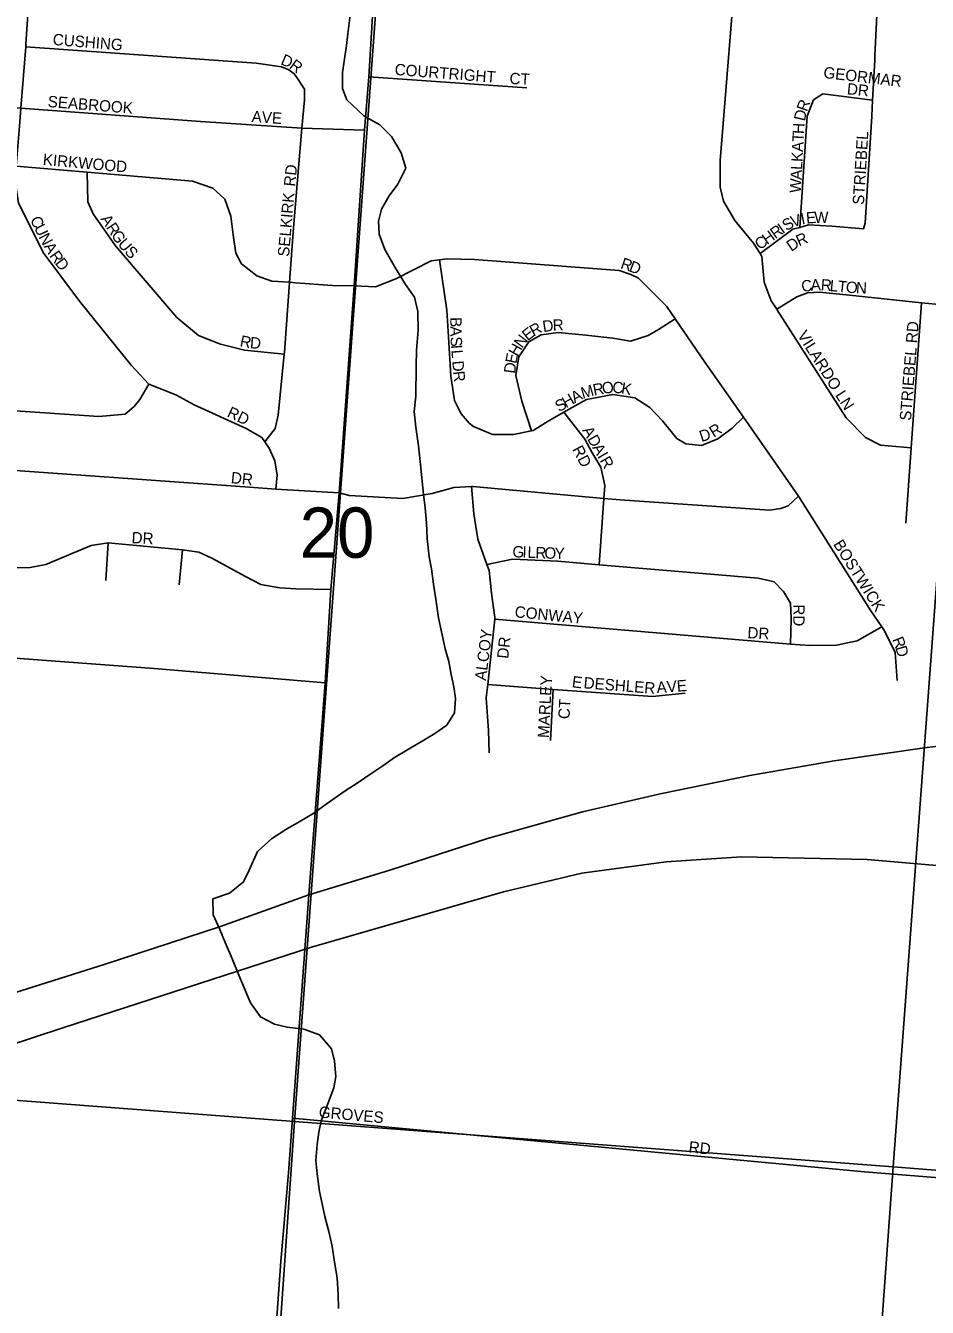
# Model space of a CAD drawing. Extents: x 0 to 34, y 0 to 22.
# Drawn here: x 5.595 to 6.347, y 18.975 to 20.042 of the extents above; entities that cross this region are included whole.
import ezdxf

# ---------------------------------------------------------------- set-up
doc = ezdxf.new("R2010")
doc.units = 0
for name, color, linetype in [('GM_X_City_Street', 7, 'Continuous'), ('GM_X_City_Street_Text', 7, 'Continuous'), ('GM_X_Interstate_Route', 7, 'Continuous'), ('GM_X_Minor_River', 7, 'Continuous'), ('GM_X_Rail_Line', 7, 'Continuous'), ('GM_X_Section', 7, 'Continuous'), ('GM_X_Section_Text', 7, 'Continuous')]:
    doc.layers.add(name, color=color, linetype=linetype)

msp = doc.modelspace()

# ---------------------------------------------------------------- linework, layer by layer
at = {"layer": 'GM_X_City_Street'}
for points in [[(5.8036, 19.6561), (5.8045, 19.6679), (5.8027, 19.6797), (5.7979, 19.6904), (5.7943, 19.6956), (5.7919, 19.6992), (5.7787, 19.7066), (5.7353, 19.7265), (5.7202, 19.7346), (5.6977, 19.7437), (5.6829, 19.7593), (5.6398, 19.8127), (5.6095, 19.8533), (5.5891, 19.8946), (5.5863, 19.9128), (5.5872, 19.9251), (5.5898, 19.9584), (5.591, 19.9736), (5.595, 20.0245), (5.5952, 20.0268), (5.6037, 20.1551)], [(5.8813, 20.0039), (5.889, 20.1337)], [(6.2229, 19.803), (6.221, 19.8061), (6.2165, 19.8131), (6.2106, 19.8287), (6.2086, 19.85), (6.2071, 19.8524), (6.2018, 19.8611), (6.1861, 19.8799), (6.1768, 19.896), (6.1739, 19.9078), (6.1738, 19.9299), (6.1886, 20.1117)], [(6.3027, 20.0134), (6.3029, 20.0172), (6.3069, 20.1022)], [(5.595, 20.0245), (5.7871, 20.0109), (5.8083, 20.008), (5.8144, 20.0053), (5.8189, 20.0022), (5.8204, 19.9999)], [(6.2935, 19.873), (6.2947, 19.8776), (6.3002, 19.9669), (6.3009, 19.9801), (6.3027, 20.0134)], [(5.7943, 19.6956), (5.803, 19.7067), (5.8054, 19.7177), (5.8104, 19.7685), (5.8106, 19.7701), (5.8149, 19.8285), (5.8182, 19.8738), (5.8253, 19.9567), (5.8274, 19.9805), (5.8275, 19.9892), (5.8204, 19.9999)], [(5.8447, 19.4949), (5.8493, 19.5725), (5.8563, 19.6532), (5.8687, 19.8255), (5.8774, 19.9551), (5.881, 19.9996), (5.8813, 20.0039)], [(5.881, 19.9996), (6.0126, 19.9905)], [(5.4485, 19.9847), (5.4785, 19.9823), (5.5353, 19.9778), (5.5551, 19.9763), (5.591, 19.9736), (5.7406, 19.9624), (5.8253, 19.9567), (5.8774, 19.9551)], [(6.2402, 19.8741), (6.2463, 19.9667), (6.2518, 19.9803)], [(6.2518, 19.9803), (6.2594, 19.9855), (6.3009, 19.9801)], [(5.5872, 19.9251), (5.6463, 19.9201), (5.734, 19.9127), (5.751, 19.9068), (5.7611, 19.8976), (5.7659, 19.8835), (5.768, 19.8679), (5.7701, 19.8526), (5.7749, 19.8438), (5.7877, 19.8338), (5.8002, 19.8295), (5.8149, 19.8285), (5.8199, 19.8281), (5.8507, 19.8259), (5.8687, 19.8255), (5.8867, 19.8247), (5.9035, 19.8314), (5.9329, 19.8463), (5.9398, 19.8472), (5.9462, 19.848), (5.969, 19.8474), (6.0896, 19.8384), (6.0994, 19.8349), (6.1058, 19.8318)], [(5.6463, 19.9201), (5.6468, 19.8954), (5.6513, 19.8855), (5.67, 19.8587), (5.7209, 19.7992), (5.739, 19.7842), (5.7575, 19.7768), (5.7775, 19.772), (5.8104, 19.7685)], [(6.2071, 19.8524), (6.2346, 19.8726), (6.2402, 19.8741), (6.2476, 19.8762), (6.2669, 19.8752), (6.2935, 19.873)], [(5.9648, 19.711), (5.958, 19.719), (5.9525, 19.7301), (5.9493, 19.7503), (5.9474, 19.783), (5.9461, 19.8051), (5.9398, 19.8472)], [(6.3215, 19.4968), (6.3198, 19.52), (6.3109, 19.538), (6.3086, 19.5414), (6.2994, 19.5548), (6.2393, 19.6502), (6.1934, 19.7162), (6.1612, 19.762), (6.1365, 19.7981), (6.1291, 19.8087), (6.1182, 19.8195), (6.1058, 19.8318)], [(6.221, 19.8061), (6.2378, 19.8163), (6.2466, 19.8196), (6.2568, 19.8202), (6.2818, 19.8177), (6.3418, 19.8113), (6.3535, 19.8103), (6.36, 19.8097)], [(6.3287, 19.6279), (6.3331, 19.6905), (6.3418, 19.8113)], [(6.0167, 19.7048), (6.0086, 19.7295), (6.0036, 19.7508), (6.006, 19.7664), (6.0145, 19.7788), (6.0248, 19.7848), (6.0389, 19.7866), (6.062, 19.7844), (6.0844, 19.7819), (6.0992, 19.7794), (6.114, 19.7842), (6.1224, 19.7891), (6.1365, 19.7981)], [(6.3331, 19.6905), (6.3074, 19.6927), (6.2949, 19.6993), (6.2788, 19.7155), (6.2237, 19.8018), (6.2229, 19.803)], [(5.5824, 19.7216), (5.6559, 19.7168), (5.6779, 19.7187), (5.6855, 19.7251), (5.6901, 19.7308), (5.6977, 19.7437)], [(5.9648, 19.711), (5.9682, 19.7083), (5.984, 19.7016), (6.0015, 19.7018), (6.0167, 19.7048), (6.0179, 19.7051), (6.032, 19.7137), (6.0437, 19.7203), (6.0626, 19.7308), (6.0843, 19.7351), (6.1028, 19.7323), (6.1153, 19.7241), (6.1258, 19.713), (6.1377, 19.6984), (6.1453, 19.6938), (6.1582, 19.6925), (6.1719, 19.698), (6.1838, 19.707), (6.1934, 19.7162)], [(6.0731, 19.5932), (6.077, 19.6485), (6.0777, 19.6592), (6.0745, 19.6744), (6.067, 19.687), (6.0611, 19.6978), (6.0437, 19.7203)], [(5.295, 19.7051), (5.3014, 19.6952), (5.3158, 19.6927), (5.3556, 19.6896), (5.5301, 19.6759), (5.5471, 19.6746), (5.7816, 19.6579), (5.8036, 19.6561), (5.8563, 19.6532), (5.8646, 19.6509), (5.9094, 19.6485), (5.9337, 19.6524), (5.952, 19.6575), (5.9667, 19.6584), (5.9676, 19.6585), (6.077, 19.6485), (6.0905, 19.6473), (6.2149, 19.6386), (6.2244, 19.6401), (6.2305, 19.6423), (6.2393, 19.6502)], [(5.9814, 19.4364), (5.9809, 19.455), (5.9789, 19.4824), (5.9801, 19.4933), (5.986, 19.5479), (5.9861, 19.5492), (5.9833, 19.5694), (5.9812, 19.5884), (5.9795, 19.5933), (5.972, 19.6144), (5.9685, 19.6357), (5.9667, 19.6584)], [(5.5768, 19.5906), (5.5986, 19.5908), (5.6119, 19.5933), (5.6344, 19.6029), (5.6497, 19.6092), (5.6637, 19.6113), (5.7258, 19.6055), (5.7392, 19.6037), (5.7501, 19.5986), (5.7781, 19.5835), (5.7909, 19.5768), (5.8068, 19.574), (5.8201, 19.5731), (5.8493, 19.5725)], [(5.6619, 19.5802), (5.6637, 19.6113)], [(5.7229, 19.5765), (5.7258, 19.6055)], [(5.9795, 19.5933), (6.0007, 19.5977), (6.0386, 19.5961), (6.0731, 19.5932), (6.2055, 19.5821), (6.2188, 19.5789), (6.2267, 19.5709), (6.2326, 19.5613), (6.2332, 19.5484), (6.2324, 19.5271)], [(5.1165, 19.5549), (5.2089, 19.5439), (5.3102, 19.5362), (5.3432, 19.5337), (5.4554, 19.5251), (5.702, 19.5068), (5.8447, 19.4949)], [(5.986, 19.5479), (6.2324, 19.5271), (6.2485, 19.5258), (6.2709, 19.5263), (6.2881, 19.5299), (6.3086, 19.5414)], [(5.8137, 19.0835), (5.814, 19.0866), (5.8173, 19.1321), (5.8311, 19.3182), (5.8447, 19.4949)], [(5.9801, 19.4933), (6.0348, 19.4894), (6.1175, 19.4835), (6.1448, 19.4863)], [(6.0324, 19.4468), (6.0348, 19.4894)], [(5.8173, 19.1321), (6.2942, 19.0874), (6.8177, 19.0455)], [(5.7871, 18.7424), (5.7915, 18.7961), (5.7957, 18.8469), (5.8078, 19.0127), (5.8137, 19.0835)]]:
    msp.add_lwpolyline(points, dxfattribs=at)
at = {"layer": 'GM_X_Interstate_Route'}
msp.add_lwpolyline([(5.515, 19.2145), (5.6613, 19.2604), (5.7565, 19.2916), (5.8311, 19.3182), (5.8985, 19.3388), (5.98, 19.3651), (6.059, 19.3874), (6.1254, 19.4026), (6.1987, 19.4177), (6.2689, 19.4298), (6.3443, 19.4407), (6.4452, 19.453), (6.6369, 19.476), (6.6854, 19.482), (6.8515, 19.5006)], dxfattribs=at)
at = {"layer": 'GM_X_Minor_River'}
for points in [[(5.8591, 20.0033), (5.8604, 20.0127), (5.8624, 20.0256), (5.8636, 20.0355), (5.8669, 20.062)], [(5.8558, 18.9738), (5.8555, 18.9852), (5.8545, 18.9993), (5.8524, 19.0122), (5.8506, 19.0255), (5.8477, 19.0377), (5.8444, 19.0502), (5.8422, 19.0609), (5.84, 19.0711), (5.8379, 19.0859), (5.8369, 19.097), (5.8381, 19.1102), (5.8394, 19.1205), (5.8414, 19.1299), (5.8456, 19.1405), (5.8518, 19.1576), (5.8534, 19.167), (5.8524, 19.1796), (5.8499, 19.1899), (5.8398, 19.2017), (5.8269, 19.2064), (5.8129, 19.208), (5.8024, 19.2104), (5.7907, 19.2165), (5.7825, 19.2284), (5.7728, 19.2512), (5.7673, 19.2645), (5.7614, 19.2786), (5.7569, 19.2893), (5.7514, 19.3015), (5.7511, 19.3148), (5.7648, 19.3196), (5.7766, 19.329), (5.7813, 19.3388), (5.7882, 19.3543), (5.8, 19.3649), (5.8119, 19.3727), (5.8229, 19.3791), (5.8351, 19.3862), (5.8454, 19.3937), (5.8614, 19.405), (5.8721, 19.4117), (5.8827, 19.4189), (5.8926, 19.4256), (5.9025, 19.4327), (5.9128, 19.4387), (5.9254, 19.4462), (5.9361, 19.4526), (5.946, 19.4597), (5.9525, 19.4699), (5.9534, 19.4817), (5.952, 19.4916), (5.9498, 19.5018), (5.9476, 19.5125), (5.9447, 19.5231), (5.9421, 19.5349), (5.9392, 19.549), (5.9371, 19.5627), (5.935, 19.5771), (5.9332, 19.5897), (5.9314, 19.5999), (5.9297, 19.6151), (5.929, 19.6277), (5.928, 19.6406), (5.9266, 19.6516), (5.9252, 19.6656), (5.9238, 19.6793), (5.9224, 19.6922), (5.9203, 19.7078), (5.9189, 19.7207), (5.9202, 19.7336), (5.9204, 19.7583), (5.9209, 19.772), (5.9222, 19.7887), (5.922, 19.8042), (5.9191, 19.816), (5.9116, 19.8267), (5.9023, 19.8416), (5.8945, 19.8557), (5.8897, 19.8686), (5.889, 19.8793), (5.8917, 19.8895), (5.8979, 19.9005), (5.9052, 19.9103), (5.9118, 19.9235), (5.9081, 19.9364), (5.8999, 19.9498), (5.8901, 19.9597), (5.877, 19.9671), (5.8627, 19.9805), (5.859, 19.99), (5.8591, 20.0033)]]:
    msp.add_lwpolyline(points, dxfattribs=at)
at = {"layer": 'GM_X_Rail_Line'}
msp.add_lwpolyline([(3.2423, 18.4276), (4.0405, 18.6814), (4.9172, 18.9741), (5.626, 19.2074), (5.8332, 19.2746), (5.9934, 19.3207), (6.0587, 19.3362), (6.1289, 19.3456), (6.1917, 19.3498), (6.2964, 19.3477), (6.6636, 19.3159)], dxfattribs=at)
at = {"layer": 'GM_X_Section'}
for points in [[(5.3911, 20.1713), (5.8928, 20.1355), (5.819, 19.1295), (5.3184, 19.1674)], [(5.8928, 20.1355), (6.3931, 20.0998), (6.3181, 19.0917), (5.819, 19.1295)], [(6.3931, 20.0998), (6.8995, 20.0595), (6.8218, 19.0519), (6.3181, 19.0917)], [(5.819, 19.1295), (5.7484, 18.1169), (5.2507, 18.1559), (5.3184, 19.1674)], [(6.3181, 19.0917), (6.2447, 18.0791), (6.2087, 18.0808), (5.7484, 18.1169), (5.819, 19.1295)], [(6.3181, 19.0917), (6.8218, 19.0519), (6.7511, 18.0375), (6.2447, 18.0791)]]:
    msp.add_lwpolyline(points, close=True, dxfattribs=at)

# ---------------------------------------------------------------- texts
at = {"layer": 'GM_X_City_Street_Text'}
for s, rotation, p in [('CUSHING', 355.3919, (5.6173, 20.0262)), ('D', 337.1918, (5.8069, 20.0102)), ('R', 323.9851, (5.8141, 20.0073)), ('COURTRIGHT', 355.5526, (5.9023, 20.0012)), ('GEORMAR', 353.387, (6.2596, 19.9987)), ('CT', 356.8222, (5.9981, 19.9937)), ('DR', 353.9832, (6.2792, 19.9851)), ('SEABROOK', 355.4286, (5.6131, 19.9745)), ('R', 70.1768, (6.2462, 19.97)), ('AVE', 356.0569, (5.7831, 19.962)), ('D', 76.9313, (6.2444, 19.9622)), ('H', 87.0631, (6.2438, 19.9518)), ('A', 87.0631, (6.243, 19.9369)), ('T', 87.0631, (6.2434, 19.9452)), ('STRIEBEL', 86.477, (6.2937, 19.8928)), ('KIRKWOOD', 354.8056, (5.609, 19.9262)), ('K', 87.0631, (6.2426, 19.9285)), ('RD', 83.9832, (5.8195, 19.9079)), ('A', 87.0631, (6.2418, 19.9136)), ('L', 87.0631, (6.2422, 19.9219)), ('W', 87.0631, (6.2412, 19.9027)), ('SELKIRK', 85.1569, (5.8145, 19.8495)), ('C', 295.8641, (5.5984, 19.8808)), ('A', 303.296, (5.657, 19.8812)), ('S', 32.4775, (6.2293, 19.8708)), ('V', 16.873, (6.2343, 19.8741)), ('I', 11.4385, (6.242, 19.8765)), ('E', 4.2394, (6.2458, 19.8773)), ('W', 0.3867, (6.2523, 19.8778)), ('U', 295.8641, (5.6017, 19.8741)), ('N', 297.7704, (5.6055, 19.8663)), ('R', 303.2724, (5.6616, 19.8742)), ('G', 304.1177, (5.6658, 19.8678)), ('H', 35.3584, (6.213, 19.8593)), ('R', 35.3694, (6.2198, 19.8642)), ('I', 35.3395, (6.226, 19.8685)), ('R', 23.425, (6.2396, 19.8582)), ('A', 301.5831, (5.6097, 19.8583)), ('U', 310.9385, (5.6712, 19.86)), ('S', 312.8781, (5.6769, 19.8534)), ('C', 35.3542, (6.2069, 19.855)), ('D', 34.3993, (6.2332, 19.8537)), ('R', 305.3957, (5.6144, 19.8506)), ('D', 307.3021, (5.619, 19.8443)), ('R', 341.0813, (6.0902, 19.8403)), ('D', 338.917, (6.0972, 19.8379)), ('C', 8.9474, (6.2423, 19.8202)), ('A', 2.9082, (6.2495, 19.8214)), ('R', 355.5026, (6.2575, 19.8218)), ('L', 354.4444, (6.2649, 19.8212)), ('T', 354.3628, (6.2715, 19.8206)), ('O', 355.6798, (6.2784, 19.8199)), ('N', 356.9306, (6.2869, 19.8193)), ('B', 270.0729, (5.9489, 19.7994)), ('R', 28.814, (6.0183, 19.7831)), ('D', 8.2476, (6.0265, 19.7869)), ('R', 2.575, (6.0345, 19.788)), ('STRIEBEL RD', 85.4518, (6.3329, 19.7129)), ('R', 348.2852, (5.773, 19.7752)), ('A', 270.5787, (5.9489, 19.7918)), ('N', 53.1257, (6.0088, 19.773)), ('E', 38.0498, (6.0134, 19.7792)), ('VILARDO LN', 302.3681, (6.2378, 19.7845)), ('D', 355.9749, (5.7817, 19.7735)), ('S', 273.3921, (5.949, 19.783)), ('I', 274.3992, (5.9495, 19.7761)), ('H', 61.0006, (6.005, 19.766)), ('L', 274.5564, (5.9498, 19.7719)), ('D', 274.5878, (5.9505, 19.7628)), ('E', 78.6418, (6.0039, 19.7602)), ('R', 276.6631, (5.9512, 19.7541)), ('D', 82.7693, (6.0029, 19.7521)), ('M', 16.073, (6.0593, 19.7314)), ('R', 10.2527, (6.0687, 19.7341)), ('O', 7.9601, (6.076, 19.7354)), ('C', 354.722, (6.0837, 19.7365)), ('K', 350.0705, (6.0909, 19.7359)), ('S', 29.7686, (6.0396, 19.7201)), ('H', 29.7828, (6.0454, 19.7234)), ('A', 29.0291, (6.0526, 19.7275)), ('RD', 334.8032, (5.7621, 19.7168)), ('R', 31.7046, (6.1685, 19.6989)), ('A', 300.2328, (6.0586, 19.7052)), ('D', 300.214, (6.0628, 19.698)), ('D', 17.882, (6.1583, 19.6953)), ('RD', 297.8914, (6.0503, 19.6894)), ('A', 300.2232, (6.067, 19.6908)), ('I', 300.1841, (6.0712, 19.6836)), ('R', 299.4768, (6.0732, 19.6801)), ('DR', 353.9946, (5.7657, 19.6612)), ('DR', 356.9884, (5.6831, 19.6112)), ('BOSTWICK', 302.1721, (6.2678, 19.6103)), ('G', 357.5731, (6.0006, 19.5995)), ('I', 357.5522, (6.0089, 19.5992)), ('L', 357.5793, (6.0131, 19.599)), ('R', 357.5706, (6.0197, 19.5987)), ('O', 357.5608, (6.0272, 19.5984)), ('Y', 358.7993, (6.0358, 19.598)), ('RD', 270, (6.2348, 19.5602)), ('CONWAY', 354.3817, (6.0023, 19.5495)), ('ALCOY', 82.8744, (5.9787, 19.4963)), ('DR', 356.989, (6.1964, 19.532)), ('DR', 83.982, (5.9972, 19.5146)), ('R', 291.5083, (6.3171, 19.531)), ('D', 286.0775, (6.3198, 19.5242)), ('MARLEY', 87.0907, (6.0312, 19.4487)), ('E', 352.8783, (6.0499, 19.4912)), ('DESHLER', 355.4612, (6.0598, 19.4903)), ('AVE', 4.0834, (6.1212, 19.4862)), ('CT', 86.8215, (6.0483, 19.4644)), ('GROVES', 354.8971, (5.839, 19.1328)), ('RD', 353.9934, (6.1473, 19.1037))]:
    msp.add_text(s, height=0.00947, rotation=rotation, dxfattribs=at).set_placement(p)
at = {"layer": 'GM_X_Section_Text'}
msp.add_text('20', height=0.04186, rotation=0, dxfattribs=at).set_placement((5.8234, 19.599))

doc.saveas('drawing.dxf')
